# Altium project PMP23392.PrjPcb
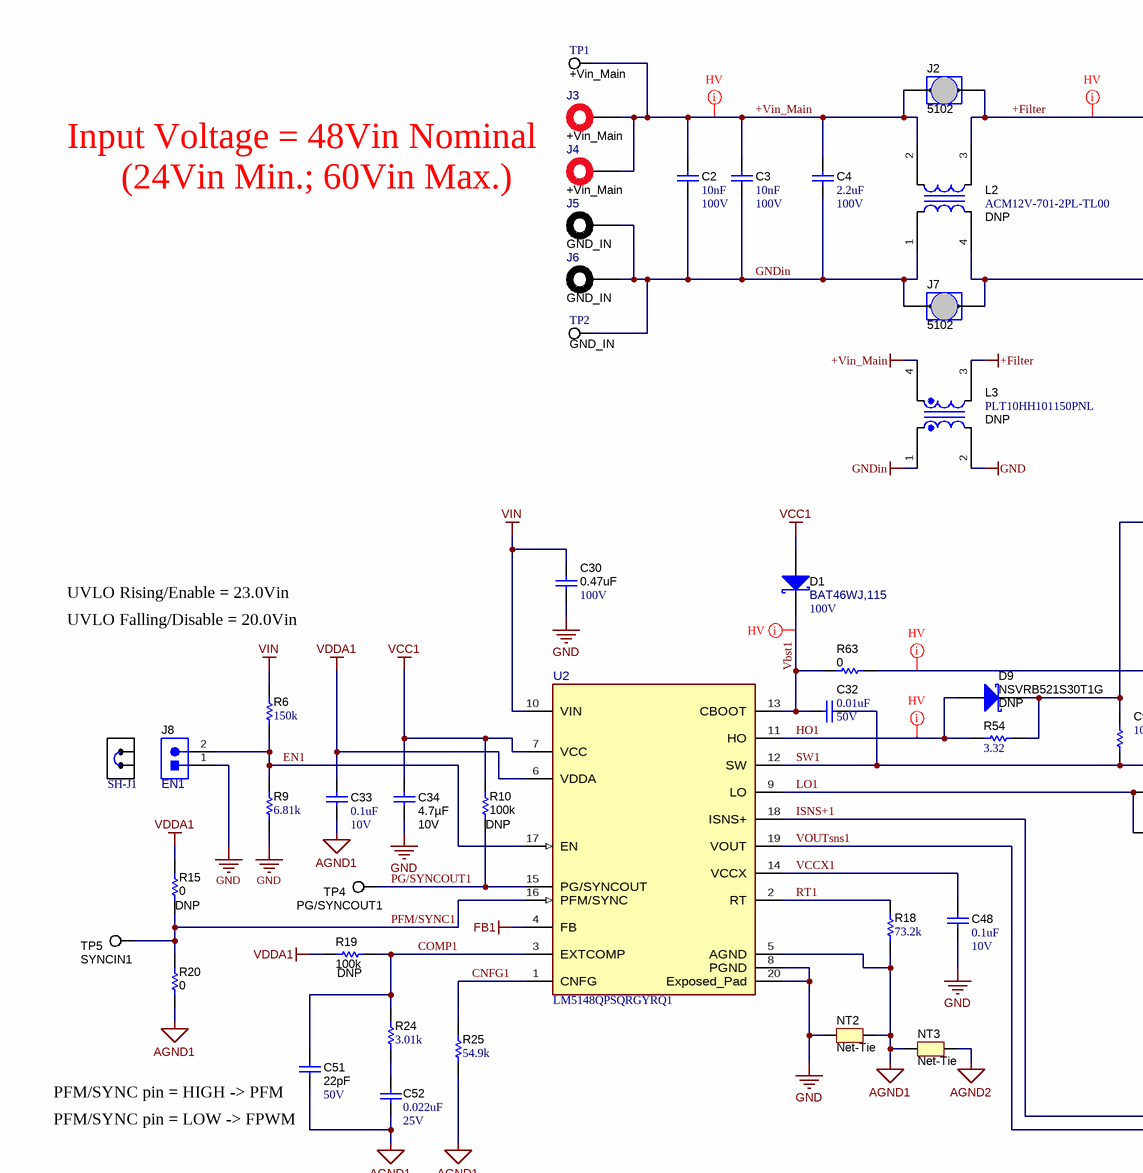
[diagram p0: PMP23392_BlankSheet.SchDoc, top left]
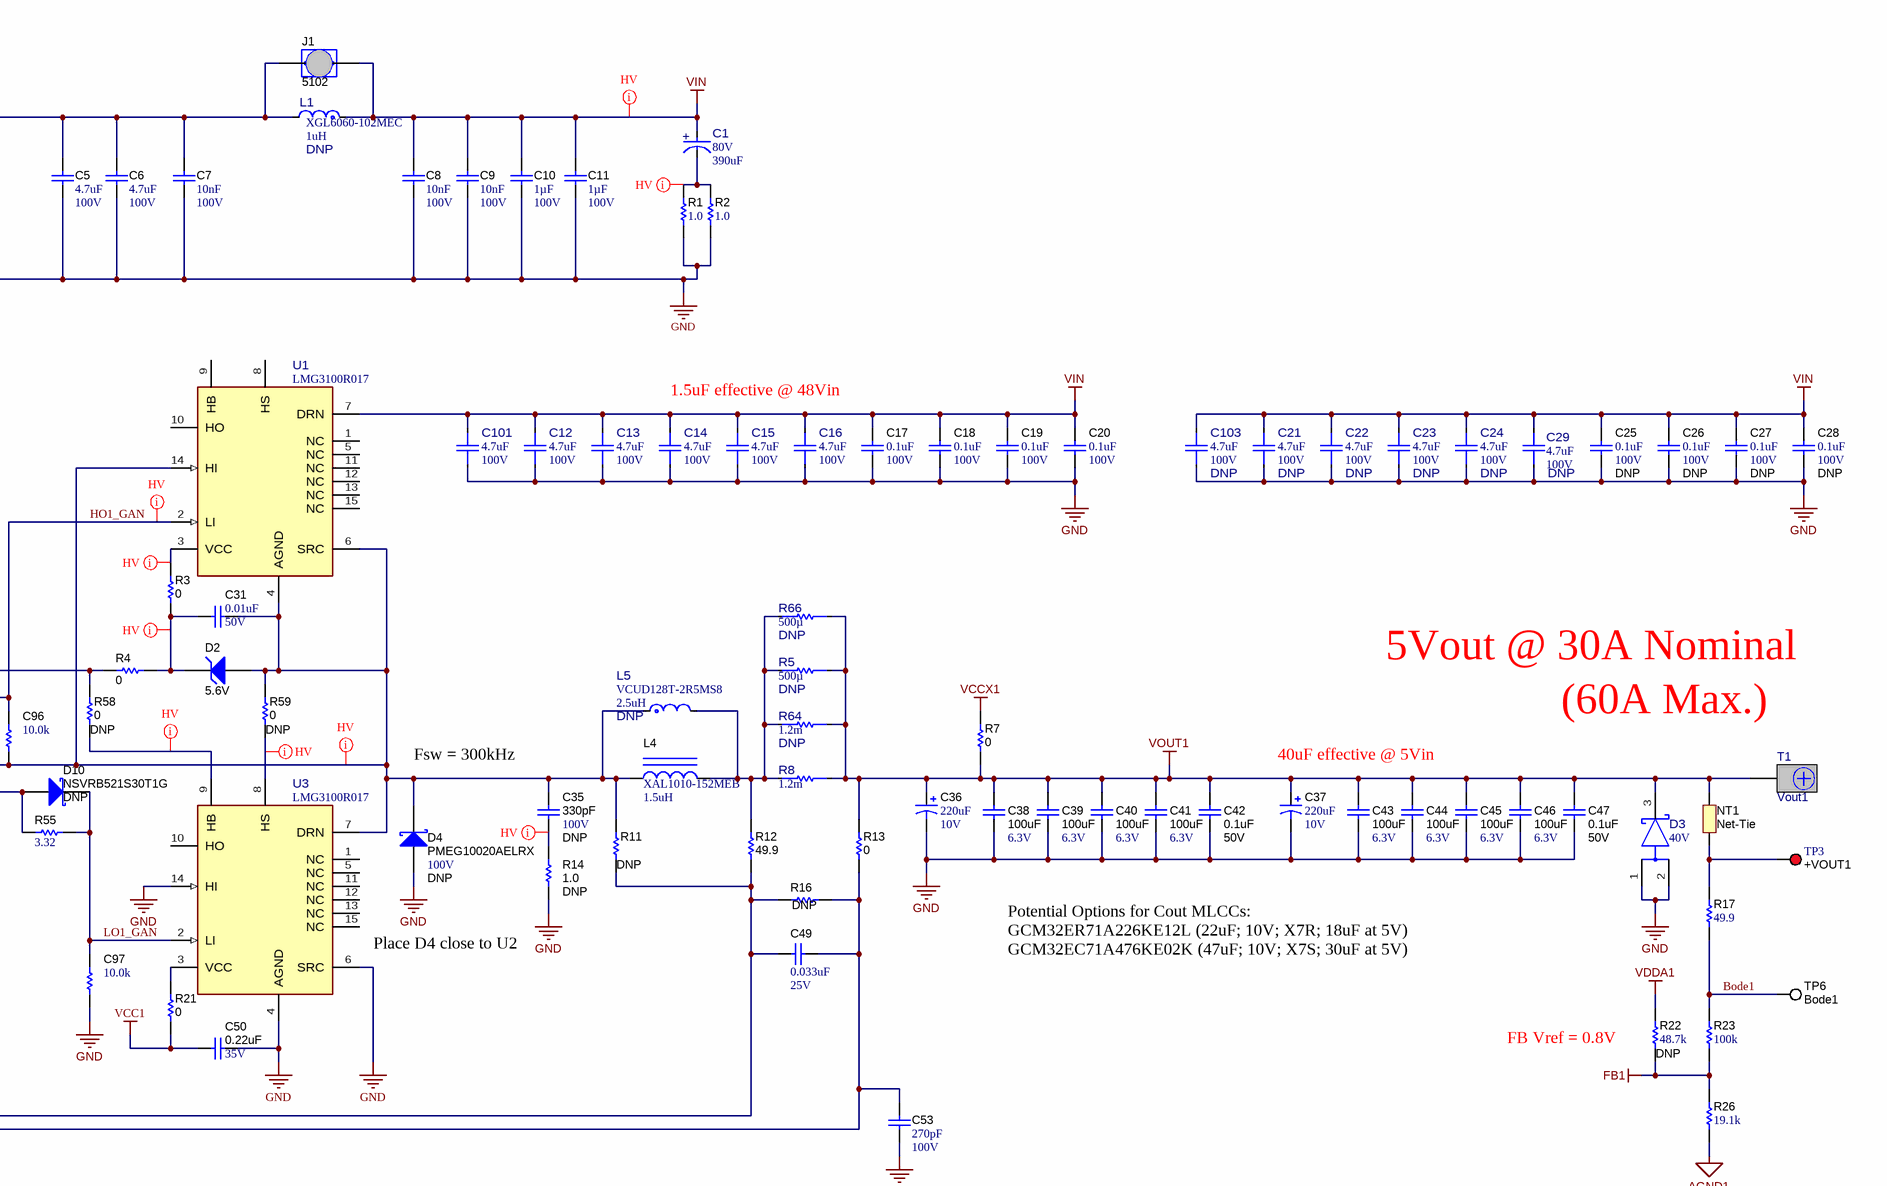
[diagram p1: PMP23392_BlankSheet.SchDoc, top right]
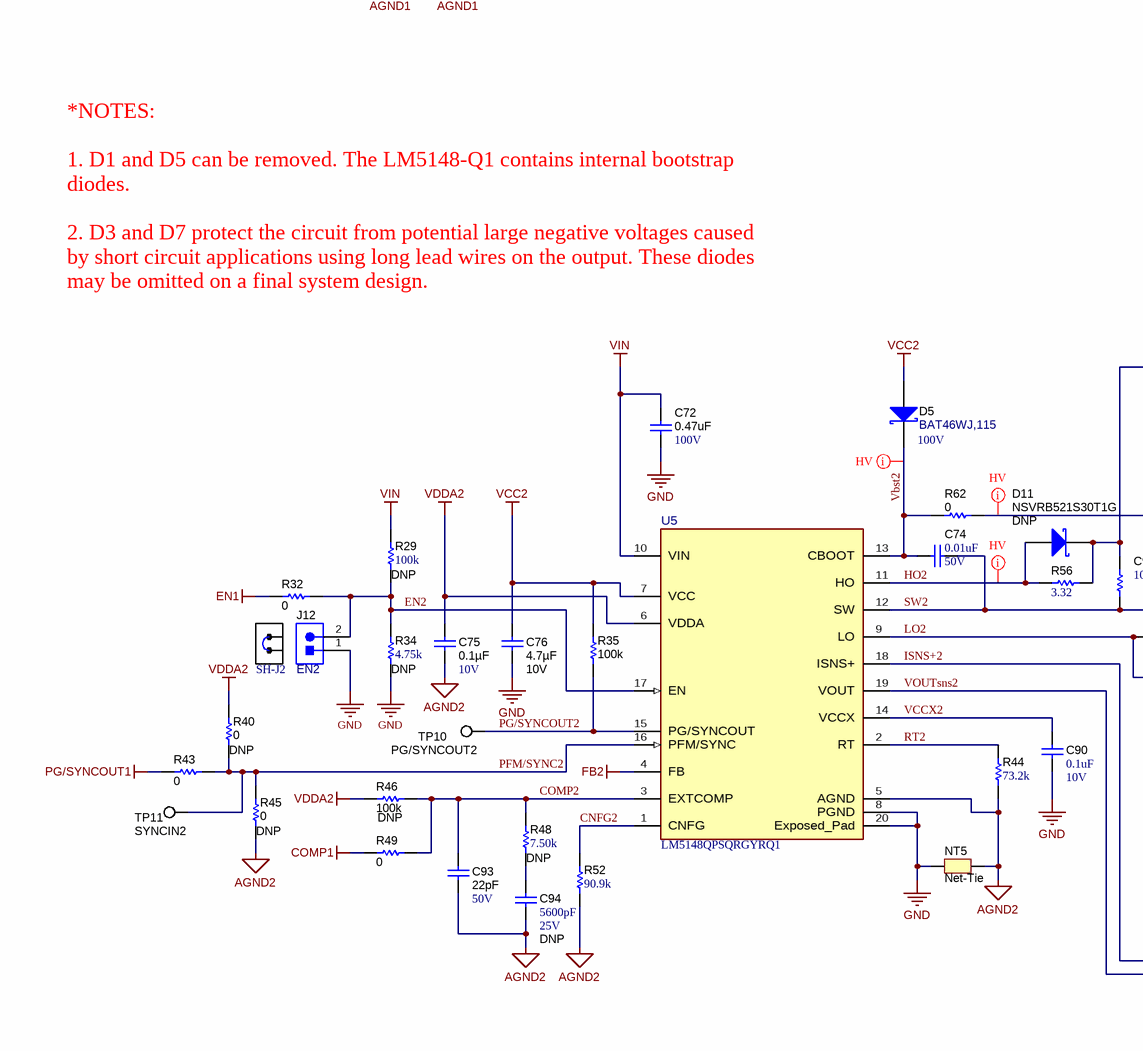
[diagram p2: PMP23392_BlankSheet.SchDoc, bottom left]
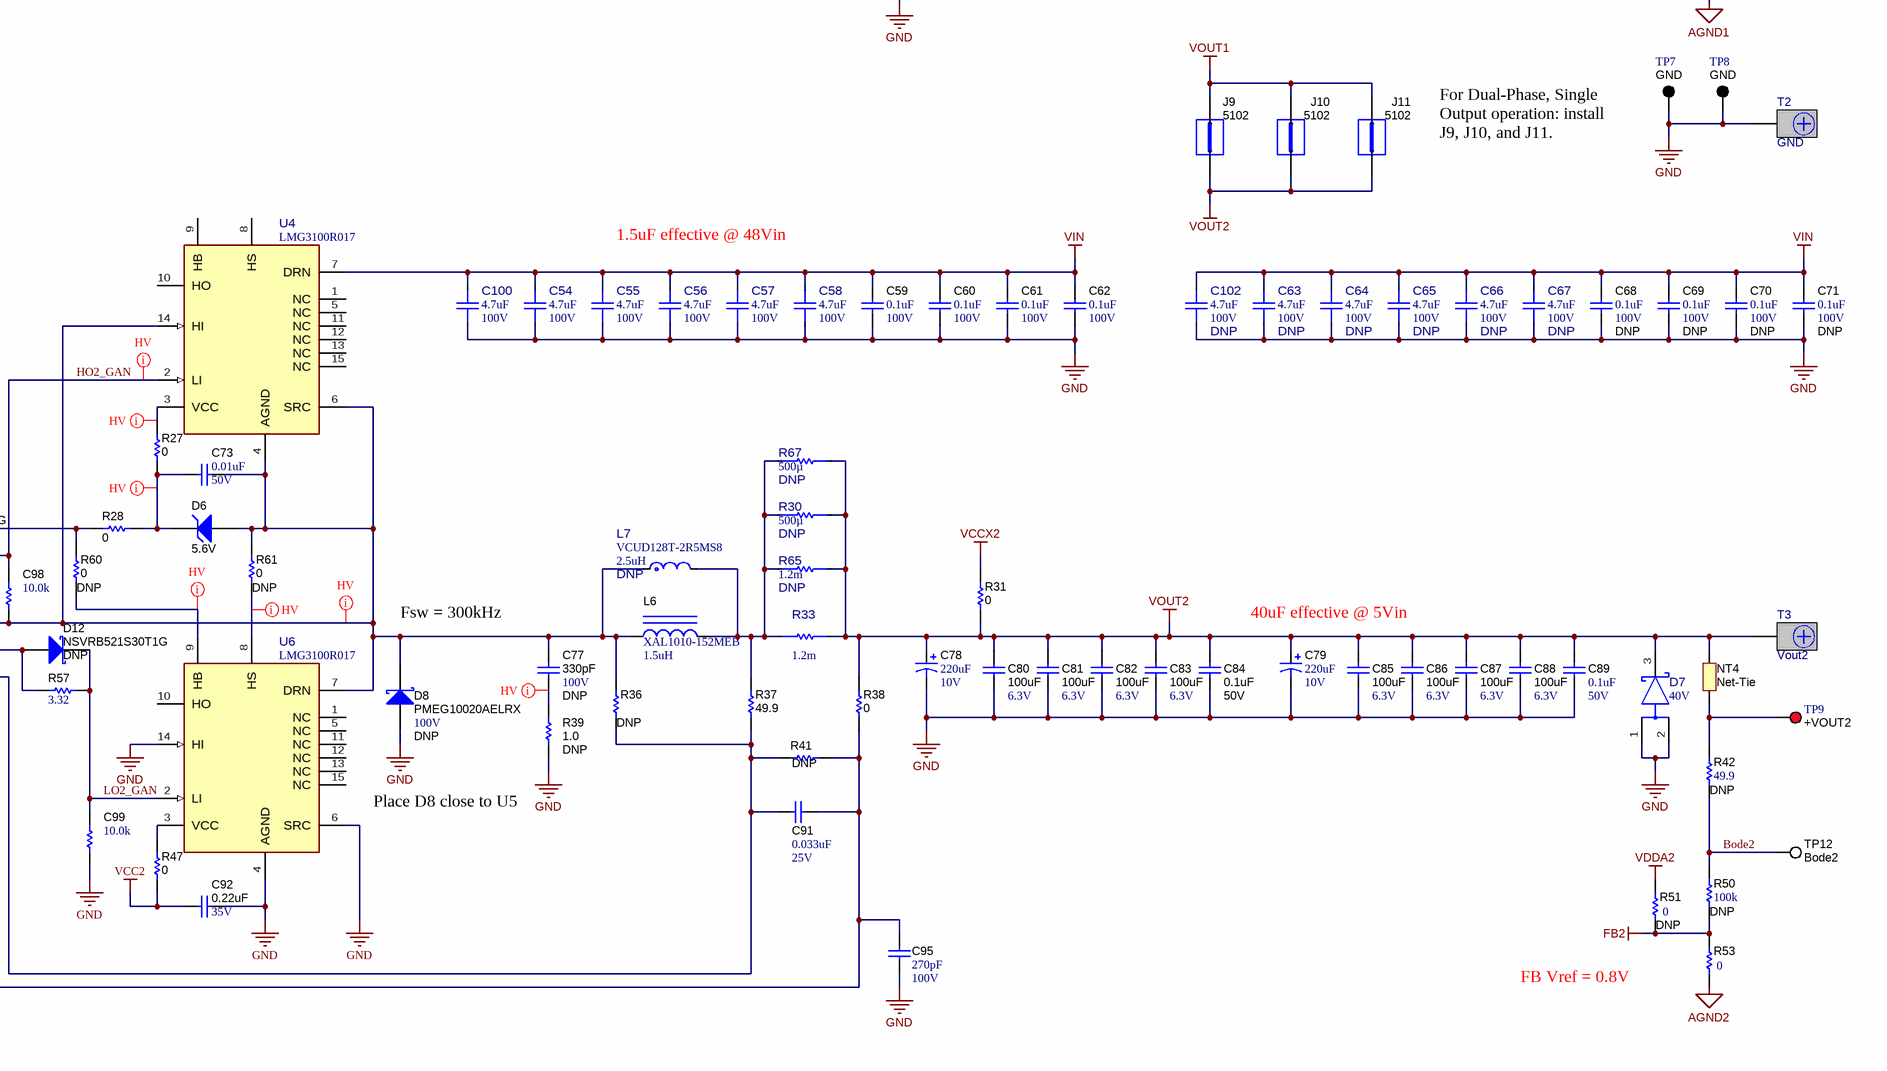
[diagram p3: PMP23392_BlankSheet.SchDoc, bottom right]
CopyrightYear: 2024; PCB_Layout: Hrag Kasparian; PCB_Rev: A; PRJ_Engineer: Hrag Kasparian; PRJ_Number: PMP23392; PRJ_Title: Dual-Phase LM5148-Q1 Buck Using GaN FETs; SCH_Rev: -1; TechSupport: http://www.ti.com/support; TID: PMP23392
2 sheets, 248 parts. Net scope: global (net labels, ports and power ports of the same name join across sheets).
Board file: PMP23392.PcbDoc
Sheets:
  PMP23392_BlankSheet.SchDoc
  PMP23392_Hardware.SchDoc

## Sheet PMP23392_BlankSheet.SchDoc
size 558 x 431 mm; Date: Not shown in title block; ApprovedBy: Not shown in title block; CheckedBy: Not shown in title block; Author: Not shown in title block; CompanyName: Not shown in title block; Engineer: Not shown in title block; Organization: Not shown in title block; Address1: Not shown in title block; Address2: Not shown in title block; Address3: Not shown in title block; Address4: Not shown in title block; DocumentNumber: 1; Revision: Use project parameter SCH_Rev; SheetNumber: 1; SheetTotal: 2; PageSetup: Record=PageOptions¦CenterHorizontal=True¦CenterVertical=True¦PrintScale=1.00¦XCorrection=1.00¦YCorrection=1.00¦PrintKind=0¦BorderSize=5000000¦LeftOffset=0¦BottomOffset=0¦Orientation=2¦PaperLength=1000¦PaperWidth=1000¦Scale=100¦PaperSource=15¦PrintQuality=600¦MediaType=1¦DitherType=10¦PaperKind=Letter¦PrintScaleMode=1; SPICEModelCacheOPLTMGFQ: <root> / <DocumentId>OPLTMGFQ</DocumentId> / <CacheFrame Number="0"> / <Model Name="zener" Kind="MDL"> / <Text>*ZENER / *Default Zener 10V @ 10mA / *Zener Diode Pinout: A,K / .MODEL ZENER D( BV=10 IBV=10E-3 )</Text> / </Model> / <Model Name="skydiode" Kind="MDL"> / <Text>*Default Schottky Diode / *Schottky Diode Pinout: A,K / .MODEL SKYDIODE D(EG=0.69 XTI=2)</Text> / </Model> / </CacheFrame> / </root>

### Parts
C1  VDC_V: 80V  ValueDisplayed: 390uF  [FP-EEE-TP1K391V_SMT_CAP_17MM0_17MM0-MFG]  (hidden comment: EEE-TP1K391V)
C2  Cap_F: 10nF  VDC_V: 100V  [0603_HV]  (hidden comment: GCM188R72A103KA37J)
C3  Cap_F: 10nF  VDC_V: 100V  [0603_HV]  (hidden comment: GCM188R72A103KA37J)
C4  VDC_V: 100V  ValueDisplayed: 2.2uF  [1206_180]  (hidden comment: CGA5L3X7S2A225K160AB)
C5  ValueDisplayed: 4.7uF  VDC_V: 100V  [1210_220]  (hidden comment: C3225X7S2A475K200AB)
C6  ValueDisplayed: 4.7uF  VDC_V: 100V  [1210_220]  (hidden comment: CGA6M3X7S2A475K200AB)
C7  Cap_F: 10nF  VDC_V: 100V  [0603L]  (hidden comment: GCM188R72A103KA37J)
C8  Cap_F: 10nF  VDC_V: 100V  [0603]  (hidden comment: GCM188R72A103KA37J)
C9  Cap_F: 10nF  VDC_V: 100V  [0603]  (hidden comment: GCM188R72A103KA37J)
C10  Cap_F: 1µF  VDC_V: 100V  [0805_150]  (hidden comment: 08051C105K4Z2A)
C11  Cap_F: 1µF  VDC_V: 100V  [0805_150]  (hidden comment: 08051C105K4Z2A)
C12  ValueDisplayed: 4.7uF  VDC_V: 100V  [FP-GCJ32DC72A475KE01L_1210-MFG]  (hidden comment: GCJ32DC72A475KE01L)
C13  ValueDisplayed: 4.7uF  VDC_V: 100V  [FP-GCJ32DC72A475KE01L_1210-MFG]  (hidden comment: GCJ32DC72A475KE01L)
C14  ValueDisplayed: 4.7uF  VDC_V: 100V  [FP-GCJ32DC72A475KE01L_1210-MFG]  (hidden comment: GCJ32DC72A475KE01L)
C15  ValueDisplayed: 4.7uF  VDC_V: 100V  [FP-GCJ32DC72A475KE01L_1210-MFG]  (hidden comment: GCJ32DC72A475KE01L)
C16  ValueDisplayed: 4.7uF  VDC_V: 100V  [FP-GCJ32DC72A475KE01L_1210-MFG]  (hidden comment: GCJ32DC72A475KE01L)
C17  VDC_V: 100V  ValueDisplayed: 0.1uF  [0603L]  (hidden comment: GCJ188R72A104KA01D)
C18  VDC_V: 100V  ValueDisplayed: 0.1uF  [0603L]  (hidden comment: GCJ188R72A104KA01D)
C19  VDC_V: 100V  ValueDisplayed: 0.1uF  [0603L]  (hidden comment: GCJ188R72A104KA01D)
C20  VDC_V: 100V  ValueDisplayed: 0.1uF  [0603L]  (hidden comment: GCJ188R72A104KA01D)
C21  DNP  ValueDisplayed: 4.7uF  VDC_V: 100V  [FP-GCJ32DC72A475KE01L_1210-MFG]
C22  DNP  ValueDisplayed: 4.7uF  VDC_V: 100V  [FP-GCJ32DC72A475KE01L_1210-MFG]
C23  DNP  ValueDisplayed: 4.7uF  VDC_V: 100V  [FP-GCJ32DC72A475KE01L_1210-MFG]
C24  DNP  ValueDisplayed: 4.7uF  VDC_V: 100V  [FP-GCJ32DC72A475KE01L_1210-MFG]
C25  DNP  VDC_V: 100V  ValueDisplayed: 0.1uF  [0603L]
C26  DNP  VDC_V: 100V  ValueDisplayed: 0.1uF  [0603L]
C27  DNP  VDC_V: 100V  ValueDisplayed: 0.1uF  [0603L]
C28  DNP  VDC_V: 100V  ValueDisplayed: 0.1uF  [0603L]
C29  DNP  ValueDisplayed: 4.7uF  VDC_V: 100V  [FP-GCJ32DC72A475KE01L_1210-MFG]
C30  value 0.47uF  Value1: 100V  [0805L]  (hidden comment: KAF21KR72A474KU)
C31  ValueDisplayed: 0.01uF  Value2: 50V  [0402]  (hidden comment: GRM155R71H103KA88D)
C32  ValueDisplayed: 0.01uF  Value2: 50V  [0402]  (hidden comment: GRM155R71H103KA88D)
C33  value 0.1uF  Value2: 10V  [0402L]  (hidden comment: C0402C104K8RACAUTO)
C34  Cap_F: 4.7µF  Value2: 10V  [0603L]  (hidden comment: GRM188Z71A475ME15D)
C35  DNP  value 330pF  Value1: 100V  [0603L]
C36  VDC_V: 10V  ValueDisplayed: 220uF  [7343-31]
C37  VDC_V: 10V  ValueDisplayed: 220uF  [7343-31]
C38  value 100uF  Value1: 6.3V  [1210L]  (hidden comment: GRT32EC70J107ME13K)
C39  value 100uF  Value1: 6.3V  [1210L]  (hidden comment: GRT32EC70J107ME13K)
C40  value 100uF  Value1: 6.3V  [1210L]  (hidden comment: GRT32EC70J107ME13K)
C41  value 100uF  Value1: 6.3V  [1210L]  (hidden comment: GRT32EC70J107ME13K)
C42  Value2: 50V  Cap_F: 0.1uF  [0603L]  (hidden comment: C0603C104K5RACTU)
C43  value 100uF  Value1: 6.3V  [1210L]  (hidden comment: GRT32EC70J107ME13K)
C44  value 100uF  Value1: 6.3V  [1210L]  (hidden comment: GRT32EC70J107ME13K)
C45  value 100uF  Value1: 6.3V  [1210L]  (hidden comment: GRT32EC70J107ME13K)
C46  value 100uF  Value1: 6.3V  [1210L]  (hidden comment: GRT32EC70J107ME13K)
C47  ValueDisplayed: 0.1uF  Value2: 50V  [0603L]  (hidden comment: Capacitor)
C48  value 0.1uF  Value2: 10V  [0402L]  (hidden comment: C0402C104K8RACAUTO)
C49  ValueDisplayed: 0.033uF  Value2: 25V  [0402L]  (hidden comment: CGA2B1X7R1E333K050BC)
C50  value 0.22uF  Value1: 35V  [0402L]  (hidden comment: CGA2B1X7R1V224K050BC)
C51  ValueDisplayed: 22pF  Value2: 50V  [0402L]  (hidden comment: CGA2B2NP01H220J050BA)
C52  ValueDisplayed: 0.022uF  VDC_V: 25V  [0402L]  (hidden comment: GCM155R71E223KA55D)
C53  ValueDisplayed: 270pF  VDC_V: 100V  [0402L]  (hidden comment: GRM155R72A271KA01D)
C54  ValueDisplayed: 4.7uF  VDC_V: 100V  [FP-GCJ32DC72A475KE01L_1210-MFG]  (hidden comment: GCJ32DC72A475KE01L)
C55  ValueDisplayed: 4.7uF  VDC_V: 100V  [FP-GCJ32DC72A475KE01L_1210-MFG]  (hidden comment: GCJ32DC72A475KE01L)
C56  ValueDisplayed: 4.7uF  VDC_V: 100V  [FP-GCJ32DC72A475KE01L_1210-MFG]  (hidden comment: GCJ32DC72A475KE01L)
C57  ValueDisplayed: 4.7uF  VDC_V: 100V  [FP-GCJ32DC72A475KE01L_1210-MFG]  (hidden comment: GCJ32DC72A475KE01L)
C58  ValueDisplayed: 4.7uF  VDC_V: 100V  [FP-GCJ32DC72A475KE01L_1210-MFG]  (hidden comment: GCJ32DC72A475KE01L)
C59  VDC_V: 100V  ValueDisplayed: 0.1uF  [0603L]  (hidden comment: GCJ188R72A104KA01D)
C60  VDC_V: 100V  ValueDisplayed: 0.1uF  [0603L]  (hidden comment: GCJ188R72A104KA01D)
C61  VDC_V: 100V  ValueDisplayed: 0.1uF  [0603L]  (hidden comment: GCJ188R72A104KA01D)
C62  VDC_V: 100V  ValueDisplayed: 0.1uF  [0603L]  (hidden comment: GCJ188R72A104KA01D)
C63  DNP  ValueDisplayed: 4.7uF  VDC_V: 100V  [FP-GCJ32DC72A475KE01L_1210-MFG]
C64  DNP  ValueDisplayed: 4.7uF  VDC_V: 100V  [FP-GCJ32DC72A475KE01L_1210-MFG]
C65  DNP  ValueDisplayed: 4.7uF  VDC_V: 100V  [FP-GCJ32DC72A475KE01L_1210-MFG]
C66  DNP  ValueDisplayed: 4.7uF  VDC_V: 100V  [FP-GCJ32DC72A475KE01L_1210-MFG]
C67  DNP  ValueDisplayed: 4.7uF  VDC_V: 100V  [FP-GCJ32DC72A475KE01L_1210-MFG]
C68  DNP  VDC_V: 100V  ValueDisplayed: 0.1uF  [0603L]
C69  DNP  VDC_V: 100V  ValueDisplayed: 0.1uF  [0603L]
C70  DNP  VDC_V: 100V  ValueDisplayed: 0.1uF  [0603L]
C71  DNP  VDC_V: 100V  ValueDisplayed: 0.1uF  [0603L]
C72  value 0.47uF  Value1: 100V  [0805L]  (hidden comment: KAF21KR72A474KU)
C73  ValueDisplayed: 0.01uF  Value2: 50V  [0402]  (hidden comment: GRM155R71H103KA88D)
C74  ValueDisplayed: 0.01uF  Value2: 50V  [0402]  (hidden comment: GRM155R71H103KA88D)
C75  ValueDisplayed: 0.1µF  Value2: 10V  [0402L]  (hidden comment: C0402C104K8RACAUTO)
C76  Cap_F: 4.7µF  Value2: 10V  [0603L]  (hidden comment: GRM188Z71A475ME15D)
C77  DNP  value 330pF  Value1: 100V  [0603L]
C78  VDC_V: 10V  ValueDisplayed: 220uF  [7343-31]
C79  VDC_V: 10V  ValueDisplayed: 220uF  [7343-31]
C80  value 100uF  Value1: 6.3V  [1210L]  (hidden comment: GRT32EC70J107ME13K)
C81  value 100uF  Value1: 6.3V  [1210L]  (hidden comment: GRT32EC70J107ME13K)
C82  value 100uF  Value1: 6.3V  [1210L]  (hidden comment: GRT32EC70J107ME13K)
C83  value 100uF  Value1: 6.3V  [1210L]  (hidden comment: GRT32EC70J107ME13K)
C84  value 0.1uF  Value2: 50V  [0603L]  (hidden comment: C0603C104K5RACTU)
C85  value 100uF  Value1: 6.3V  [1210L]  (hidden comment: GRT32EC70J107ME13K)
C86  value 100uF  Value1: 6.3V  [1210L]  (hidden comment: GRT32EC70J107ME13K)
C87  value 100uF  Value1: 6.3V  [1210L]  (hidden comment: GRT32EC70J107ME13K)
C88  value 100uF  Value1: 6.3V  [1210L]  (hidden comment: GRT32EC70J107ME13K)
C89  value 0.1uF  VDC_V: 50V  [0603L]  (hidden comment: C0603C104K5RACTU)
C90  value 0.1uF  Value2: 10V  [0402L]  (hidden comment: C0402C104K8RACAUTO)
C91  ValueDisplayed: 0.033uF  Value2: 25V  [0402L]  (hidden comment: CGA2B1X7R1E333K050BC)
C92  value 0.22uF  Value1: 35V  [0402L]  (hidden comment: CGA2B1X7R1V224K050BC)
C93  ValueDisplayed: 22pF  Value2: 50V  [0402L]  (hidden comment: CGA2B2NP01H220J050BA)
C94  DNP  ValueDisplayed: 5600pF  VDC_V: 25V  [0402L]
C95  ValueDisplayed: 270pF  VDC_V: 100V  [0402L]  (hidden comment: GRM155R72A271KA01D)
C96  value 10.0k  [0402]  (hidden comment: CRCW040210K0FKED)
C97  value 10.0k  [0402]  (hidden comment: CRCW040210K0FKED)
C98  value 10.0k  [0402]  (hidden comment: CRCW040210K0FKED)
C99  value 10.0k  [0402]  (hidden comment: CRCW040210K0FKED)
C100  ValueDisplayed: 4.7uF  VDC_V: 100V  [FP-GCJ32DC72A475KE01L_1210-MFG]  (hidden comment: GCJ32DC72A475KE01L)
C101  ValueDisplayed: 4.7uF  VDC_V: 100V  [FP-GCJ32DC72A475KE01L_1210-MFG]  (hidden comment: GCJ32DC72A475KE01L)
C102  DNP  ValueDisplayed: 4.7uF  VDC_V: 100V  [FP-GCJ32DC72A475KE01L_1210-MFG]
C103  DNP  ValueDisplayed: 4.7uF  VDC_V: 100V  [FP-GCJ32DC72A475KE01L_1210-MFG]
D1  BAT46WJ,115  value 100V  [SOD-323F]
D2  value 5.6V  [SOD-323]  (hidden comment: TDZ5V6J,115)
D3  value 40V  [FP-SS10P4HM3_A/H_SMPC-MFG]  (hidden comment: SS10P4HM3_A/H)
D4  DNP  value 100V  PartNumber: PMEG10020AELRX  [SOD-123]
D5  BAT46WJ,115  value 100V  [SOD-323F]
D6  value 5.6V  [SOD-323]  (hidden comment: TDZ5V6J,115)
D7  value 40V  [FP-SS10P4HM3_A/H_SMPC-MFG]  (hidden comment: SS10P4HM3_A/H)
D8  DNP  value 100V  PartNumber: PMEG10020AELRX  [SOD-123]
D9  DNP  PartNumber: NSVRB521S30T1G  [SOD-523]
D10  DNP  PartNumber: NSVRB521S30T1G  [SOD-523]
D11  DNP  PartNumber: NSVRB521S30T1G  [SOD-523]
D12  DNP  PartNumber: NSVRB521S30T1G  [SOD-523]
J1  PartNumber: 5102  [Keystone_5102]
J2  PartNumber: 5102  [Keystone_5102]
J3  +Vin_Main  [Cinch_108-0902-001]
J4  +Vin_Main  [Cinch_108-0902-001]
J5  GND_IN  [Cinch_108-0903-001]
J6  GND_IN  [Cinch_108-0903-001]
J7  PartNumber: 5102  [Keystone_5102]
J8  EN1  [TSW-102-07-G-S]
J9  PartNumber: 5102  [Keystone_5102]
J10  PartNumber: 5102  [Keystone_5102]
J11  PartNumber: 5102  [Keystone_5102]
J12  EN2  [TSW-102-07-G-S]
L1  DNP  value 1uH  Part Number: XGL6060-102MEC  [FP-XGL6060-102MEC_SMT2_6MM51_6MM71-MFG]
L2  DNP  PartNumber: ACM12V-701-2PL-TL00  [TDK_ACM12V]
L3  DNP  PartNumber: PLT10HH101150PNL  [MuRata_PLT10H]
L4  value 1.5uH  [XAL1010]  (hidden comment: XAL1010-152MEB)
L5  DNP  value 2.5uH  Part Number: VCUD128T-2R5MS8  [FP-VCUD128T-2R5MS8_SMT_IND_13MM3_12MM8-MFG]
L6  value 1.5uH  [XAL1010]  (hidden comment: XAL1010-152MEB)
L7  DNP  value 2.5uH  PartNumber: VCUD128T-2R5MS8  [FP-VCUD128T-2R5MS8_SMT_IND_13MM3_12MM8-MFG]
NT1  Net-Tie  [Net-Tie_10mil]  (net tie, no BOM)
NT2  Net-Tie  [Net-Tie_10mil]  (net tie, no BOM)
NT3  Net-Tie  [Net-Tie_10mil]  (net tie, no BOM)
NT4  Net-Tie  [Net-Tie_10mil]  (net tie, no BOM)
NT5  Net-Tie  [Net-Tie_10mil]  (net tie, no BOM)
R1  ValueDisplayed: 1.0  [2512]  (hidden comment: CRCW25121R00JNEG)
R2  ValueDisplayed: 1.0  [2512]  (hidden comment: CRCW25121R00JNEG)
R3  ValueDisplayed: 0  [0402L]  (hidden comment: CRCW04020000Z0EDHP)
R4  ValueDisplayed: 0  [0402L]  (hidden comment: CRCW04020000Z0EDHP)
R5  DNP  value 500µ  [FP-PML100HZPJV0L5_1225-MFG]
R6  ValueDisplayed: 150k  [0603L]  (hidden comment: CRCW0603150KFKEA)
R7  ValueDisplayed: 0  [0402L]  (hidden comment: CRCW04020000Z0EDHP)
R8  Res_ohm: 1.2m  [FP-Y14830R00120F9R_2512-MFG]  (hidden comment: Y14830R00120F9R)
R9  ValueDisplayed: 6.81k  [0402L]  (hidden comment: CRCW04026K81FKED)
R10  DNP  ValueDisplayed: 100k  [0402L]
R11  DNP  [0603L]
R12  ValueDisplayed: 49.9  [0402L]  (hidden comment: CRCW040249R9FKED)
R13  Value1: 0  [FP-RMCF0402ZT0R00_0402 (1005 metric)-0]  (hidden comment: RMCF0402ZT0R00)
R14  DNP  value 1.0  [1210L]
R15  DNP  ValueDisplayed: 0  [0402L]
R16  DNP  [0402L]
R17  ValueDisplayed: 49.9  [0603L]  (hidden comment: CRCW060349R9FKEA)
R18  ValueDisplayed: 73.2k  [0402L]  (hidden comment: CRCW040273K2FKED)
R19  DNP  ValueDisplayed: 100k  [0402L]
R20  ValueDisplayed: 0  [0402L]
R21  ValueDisplayed: 0  [0402L]  (hidden comment: CRCW04020000Z0EDHP)
R22  DNP  ValueDisplayed: 48.7k  [0402L]
R23  ValueDisplayed: 100k  [0402L]  (hidden comment: RMCF0402FT100K)
R24  ValueDisplayed: 3.01k  [0402L]  (hidden comment: CRCW04023K01FKED)
R25  ValueDisplayed: 54.9k  [0402L]  (hidden comment: CRCW040254K9FKED)
R26  ValueDisplayed: 19.1k  [0402L]  (hidden comment: CRCW040219K1FKED)
R27  ValueDisplayed: 0  [0402L]  (hidden comment: CRCW04020000Z0EDHP)
R28  ValueDisplayed: 0  [0402L]  (hidden comment: CRCW04020000Z0EDHP)
R29  DNP  ValueDisplayed: 100k  [0603L]
R30  DNP  value 500µ  [FP-PML100HZPJV0L5_1225-MFG]
R31  ValueDisplayed: 0  [0402L]  (hidden comment: CRCW04020000Z0EDHP)
R32  ValueDisplayed: 0  [0402L]  (hidden comment: CRCW04020000Z0EDHP)
R33  Res_ohm: 1.2m  [FP-Y14830R00120F9R_2512-MFG]  (hidden comment: Y14830R00120F9R)
R34  DNP  ValueDisplayed: 4.75k  [0402L]
R35  ValueDisplayed: 100k  [0402L]  (hidden comment: RMCF0402FT100K)
R36  DNP  [0603L]
R37  ValueDisplayed: 49.9  [0402L]  (hidden comment: CRCW040249R9FKED)
R38  Value1: 0  [FP-RMCF0402ZT0R00_0402 (1005 metric)-0]  (hidden comment: RMCF0402ZT0R00)
R39  DNP  value 1.0  [1210L]
R40  DNP  ValueDisplayed: 0  [0402L]
R41  DNP  [0402L]
R42  DNP  ValueDisplayed: 49.9  [0603L]
R43  ValueDisplayed: 0  [0402L]  (hidden comment: CRCW04020000Z0EDHP)
R44  ValueDisplayed: 73.2k  [0402L]  (hidden comment: CRCW040273K2FKED)
R45  DNP  ValueDisplayed: 0  [0402L]
R46  DNP  ValueDisplayed: 100k  [0402L]
R47  ValueDisplayed: 0  [0402L]  (hidden comment: CRCW04020000Z0EDHP)
R48  DNP  ValueDisplayed: 7.50k  [0402L]
R49  ValueDisplayed: 0  [0402L]  (hidden comment: CRCW04020000Z0EDHP)
R50  DNP  ValueDisplayed: 100k  [0402L]
R51  DNP  value 0  [FP-RMCF0402ZT0R00_0402 (1005 metric)-0]
R52  ValueDisplayed: 90.9k  [0402L]  (hidden comment: CRCW040290K9FKED)
R53  value 0  [FP-RMCF0402ZT0R00_0402 (1005 metric)-0]
R54  ValueDisplayed: 3.32  [0402L]  (hidden comment: CRCW04023R32FKED)
R55  ValueDisplayed: 3.32  [0402L]  (hidden comment: CRCW04023R32FKED)
R56  ValueDisplayed: 3.32  [0402L]  (hidden comment: CRCW04023R32FKED)
R57  ValueDisplayed: 3.32  [0402L]  (hidden comment: CRCW04023R32FKED)
R58  DNP  ValueDisplayed: 0  [0402L]
R59  DNP  ValueDisplayed: 0  [0402L]
R60  DNP  ValueDisplayed: 0  [0402L]
R61  DNP  ValueDisplayed: 0  [0402L]
R62  ValueDisplayed: 0  [0402L]
R63  ValueDisplayed: 0  [0402L]
R64  DNP  Res_ohm: 1.2m  [FP-Y14830R00120F9R_2512-MFG]
R65  DNP  Res_ohm: 1.2m  [FP-Y14830R00120F9R_2512-MFG]
R66  DNP  value 500µ  [FP-PML100HZPJV0L5_1225-MFG]
R67  DNP  value 500µ  [FP-PML100HZPJV0L5_1225-MFG]
SH-J1  60900213421  [Wurth_60900213421]  (value not drawn)
SH-J2  60900213421  [Wurth_60900213421]  (value not drawn)
T1  Vout1  [CB70-14-CY]
T2  GND  [CB70-14-CY]
T3  Vout2  [CB70-14-CY]
TP1  +Vin_Main  [Testpoint_Keystone_Compact]
TP2  GND_IN  [Testpoint_Keystone_Compact]
TP3  +VOUT1  [Keystone5010]
TP4  PG/SYNCOUT1  [Keystone5012]
TP5  SYNCIN1  [Keystone5012]
TP6  Bode1  [Keystone5012]
TP7  GND  [Keystone5011]
TP8  GND  [Keystone5011]
TP9  +VOUT2  [Keystone5010]
TP10  PG/SYNCOUT2  [Keystone5012]
TP11  SYNCIN2  [Keystone5012]
TP12  Bode2  [Keystone5012]
U1  LMG3100R017  [VBE0015A-MFG]
U2  LM5148QPSQRGYRQ1  [RGY0019B-MFG]
U3  LMG3100R017  [VBE0015A-MFG]
U4  LMG3100R017  [VBE0015A-MFG]
U5  LM5148QPSQRGYRQ1  [RGY0019B-MFG]
U6  LMG3100R017  [VBE0015A-MFG]

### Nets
+Filter: C5.2 C6.2 C7.1 J1.2 J2.1 L1.2 L2.3 L3.3
+Vin_Main: C2.1 C3.1 C4.1 J2.2 J3.1 J4.1 L2.2 L3.4 TP1.1
AGND1: C33.1 C51.2 C52.2 NT2.2 NT3.1 R18.2 R20.2 R25.1 R26.1 U2.5(AGND)
AGND2: C75.1 C93.2 C94.2 NT3.2 NT5.2 R44.2 R45.2 R52.1 R53.2 U5.5(AGND)
COMP1: C51.1 R19.1 R24.2 R49.2 U2.3(EXTCOMP)
EN1: J8.2 R6.1 R9.2 R32.2 U2.17(EN)
FB1: R22.2 R23.1 R26.2 U2.4(FB)
FB2: R50.1 R51.2 R53.1 U5.4(FB)
GND: C5.1 C6.1 C7.2 C8.2 C9.2 C10.2 C11.2 C12.1 C13.1 C14.1 C15.1 C16.1 C17.2 C18.2 C19.2 C20.2 C21.1 C22.1 C23.1 C24.1 C25.2 C26.2 C27.2 C28.2 C29.1 C30.2 C34.2 C36.2(-) C37.2(-) C38.2 C39.2 C40.2 C41.2 C42.2 C43.2 C44.2 C45.2 C46.2 C47.2 C48.1 C50.2 C53.1 C54.1 C55.1 C56.1 C57.1 C58.1 C59.2 C60.2 C61.2 C62.2 C63.1 C64.1 C65.1 C66.1 C67.1 C68.2 C69.2 C70.2 C71.2 C72.2 C76.2 C78.2(-) C79.2(-) C80.2 C81.2 C82.2 C83.2 C84.2 C85.2 C86.2 C87.2 C88.2 C89.2 C90.1 C92.2 C95.1 C97.1 C99.1 C100.1 C101.1 C102.1 C103.1 D3.1(Anode) D3.2(Anode) D4.2(A) D7.1(Anode) D7.2(Anode) D8.2(A) J7.1 J8.1 J12.1 L2.4 L3.2 NT2.1 NT5.1 R1.1 R2.1 R9.1 R14.1 R34.1 R39.1 T2.1 TP7.1 TP8.1 U2.8(PGND) U2.20(Exposed_Pad) U3.4(AGND) U3.6(SRC) U3.14(HI) U5.8(PGND) U5.20(Exposed_Pad) U6.4(AGND) U6.6(SRC) U6.14(HI)
GNDin: C2.2 C3.2 C4.2 J5.1 J6.1 J7.2 L2.1 L3.1 TP2.1
PG/SYNCOUT1: R10.1 R43.2 TP4.1 U2.15(PG/SYNCOUT)
VCC1: C34.1 C50.1 D1.2(A) R10.2 R21.1 U2.7(VCC)
VCC2: C76.1 C92.1 D5.2(A) R35.2 R47.1 U5.7(VCC)
VCCX1: C48.2 R7.2 U2.14(VCCX)
VCCX2: C90.2 R31.1 U5.14(VCCX)
VDDA1: C33.2 R15.1 R19.2 R22.1 U2.6(VDDA)
VDDA2: C75.2 R40.1 R46.1 R51.1 U5.6(VDDA)
VIN: C1.2(ANODE) C8.1 C9.1 C10.1 C11.1 C12.2 C13.2 C14.2 C15.2 C16.2 C17.1 C18.1 C19.1 C20.1 C21.2 C22.2 C23.2 C24.2 C25.1 C26.1 C27.1 C28.1 C29.2 C30.1 C54.2 C55.2 C56.2 C57.2 C58.2 C59.1 C60.1 C61.1 C62.1 C63.2 C64.2 C65.2 C66.2 C67.2 C68.1 C69.1 C70.1 C71.1 C72.1 C100.2 C101.2 C102.2 C103.2 J1.1 L1.1 R6.2 R29.2 U1.7(DRN) U2.10(VIN) U4.7(DRN) U5.10(VIN)
VOUT1: C36.1(+) C37.1(+) C38.1 C39.1 C40.1 C41.1 C42.1 C43.1 C44.1 C45.1 C46.1 C47.1 D3.3(Cathode) J9.2 J10.2 J11.2 NT1.2 R5.2 R7.1 R8.2 R13.2 R64.2 R66.2 T1.1
VOUT2: C78.1(+) C79.1(+) C80.1 C81.1 C82.1 C83.1 C84.1 C85.1 C86.1 C87.1 C88.1 C89.1 D7.3(Cathode) J9.1 J10.1 J11.1 NT4.2 R30.2 R31.2 R33.2 R38.2 R65.2 R67.2 T3.1
Bode1: R17.1 R23.2 TP6.1
Bode2: R42.1 R50.2 TP12.1
CNFG1: R25.2 U2.1(CNFG)
CNFG2: R52.2 U5.1(CNFG)
COMP2: C93.1 R46.2 R48.2 R49.1 U5.3(EXTCOMP)
EN2: J12.2 R29.1 R32.1 R34.2 U5.17(EN)
HO1: D9.2(A) R54.1 U2.11(HO)
HO1_GAN: C96.2 D9.1(K) R54.2 U1.2(LI)
HO2: D11.2(A) R56.1 U5.11(HO)
HO2_GAN: C98.2 D11.1(K) R56.2 U4.2(LI)
ISNS+1: C49.2 R11.1 R12.1 R16.2 U2.18(ISNS+)
ISNS+2: C91.2 R36.1 R37.1 R41.2 U5.18(ISNS+)
LO1: D10.2(A) R55.1 U2.9(LO)
LO1_GAN: C97.2 D10.1(K) R55.2 U3.2(LI)
LO2: D12.2(A) R57.1 U5.9(LO)
LO2_GAN: C99.2 D12.1(K) R57.2 U6.2(LI)
PFM/SYNC1: R15.2 R20.1 TP5.1 U2.16(PFM/SYNC)
PFM/SYNC2: R40.2 R43.1 R45.1 TP11.1 U5.16(PFM/SYNC)
PG/SYNCOUT2: R35.1 TP10.1 U5.15(PG/SYNCOUT)
RT1: R18.1 U2.2(RT)
RT2: R44.1 U5.2(RT)
SW1: C31.2 C32.2 C35.1 C96.1 D2.2(A) D4.1(K) L4.1 L5.1 R11.2 R59.2 U1.4(AGND) U1.6(SRC) U1.14(HI) U2.12(SW) U3.7(DRN)
SW2: C73.2 C74.2 C77.1 C98.1 D6.2(A) D8.1(K) L6.1 L7.1 R36.2 R61.2 U4.4(AGND) U4.6(SRC) U4.14(HI) U5.12(SW) U6.7(DRN)
Vbst1: C32.1 D1.1(K) R63.2 U2.13(CBOOT)
Vbst2: C74.1 D5.1(K) R62.2 U5.13(CBOOT)
VOUTsns1: C49.1 C53.2 R13.1 R16.1 U2.19(VOUT)
VOUTsns2: C91.1 C95.2 R38.1 R41.1 U5.19(VOUT)
NetC1_1: C1.1(CATHODE) R1.2 R2.2
NetC31_1: C31.1 D2.1(K) R3.1 R4.1
NetC35_2: C35.2 R14.2
NetC52_1: C52.1 R24.1
NetC73_1: C73.1 D6.1(K) R27.1 R28.1
NetC77_2: C77.2 R39.2
NetC94_1: C94.1 R48.1
NetL4_2: L4.2 L5.2 R5.1 R8.1 R12.2 R64.1 R66.1
NetL6_2: L6.2 L7.2 R30.1 R33.1 R37.2 R65.1 R67.1
NetNT1_1: NT1.1 R17.2 TP3.1
NetNT4_1: NT4.1 R42.2 TP9.1
NetR3_2: R3.2 U1.3(VCC)
NetR4_2: R4.2 R58.2 R63.1
NetR21_2: R21.2 U3.3(VCC)
NetR27_2: R27.2 U4.3(VCC)
NetR28_2: R28.2 R60.2 R62.1
NetR47_2: R47.2 U6.3(VCC)
NetR58_1: R58.1 U3.9(HB)
NetR59_1: R59.1 U3.8(HS)
NetR60_1: R60.1 U6.9(HB)
NetR61_1: R61.1 U6.8(HS)

Not connected (* = marked no-connect by the designer): U1 1(NC) 5(NC) 8(HS) 9(HB) 10(HO) 11(NC) 12(NC) 13(NC) 15(NC); U3 1(NC) 5(NC) 10(HO) 11(NC) 12(NC) 13(NC) 15(NC); U4 1(NC) 5(NC) 8(HS) 9(HB) 10(HO) 11(NC) 12(NC) 13(NC) 15(NC); U6 1(NC) 5(NC) 10(HO) 11(NC) 12(NC) 13(NC) 15(NC)

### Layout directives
net class HV: +Filter, +Vin_Main, HO1, HO1_GAN, HO2, HO2_GAN, NetC1_1, NetC31_1, NetC35_2, NetC73_1, NetC77_2, NetR3_2, NetR4_2, NetR27_2, NetR28_2, NetR58_1, NetR59_1, NetR60_1, NetR61_1, SW1, SW2, Vbst1, Vbst2, VIN

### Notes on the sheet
- (near J3) Input Voltage = 48Vin Nominal
- (24Vin Min.; 60Vin Max.)
- 1.5uF effective @ 48Vin
- UVLO Rising/Enable = 23.0Vin
- UVLO Falling/Disable = 20.0Vin
- 5Vout @ 30A Nominal
- Fsw = 300kHz
- 40uF effective @ 5Vin
- (60A Max.)
- Place D4 close to U2
- Potential Options for Cout MLCCs:
  GCM32ER71A226KE12L (22uF; 10V; X7R; 18uF at 5V)
  GCM32EC71A476KE02K (47uF; 10V; X7S; 30uF at 5V)
- (near R22) FB Vref = 0.8V
- (near C51) PFM/SYNC pin = HIGH -> PFM
- (near C51) PFM/SYNC pin = LOW -> FPWM
- For Dual-Phase, Single Output operation: install J9, J10, and J11.
- *NOTES:
  1. D1 and D5 can be removed. The LM5148-Q1 contains internal bootstrap diodes.
  2. D3 and D7 protect the circuit from potential large negative voltages caused by short circuit applications using long lead wires on the output. These diodes may be omitted on a final system design.
- Place D8 close to U5
- FB Vref = 0.8V

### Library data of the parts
C1 = CMP-0048820-1: Cap Aluminum Lytic 390uF 80V 20% (16 X 16.5mm) SMD 0.1 Ohm 1900mA 3000h 125°C Automotive T/R; Manufacturer: Panasonic; Value: 390µF; SizeZ_mm: 17.1mm; AEC Qualified: No; IRMS_A: 1.9A; Dissipation Factor: 12%; Esr: 0.1; Leakage Current: 312uA; Life: 3000Hours
C2 = CMP-0084773-1: CAP, CERM, 0.01 µF, 100 V,+/- 10%, X7R, AEC-Q200 Grade 1, 0603; Manufacturer: MuRata; Polarized: N; Value: 0.01uF; ValueDisplayed: 0.01µF; U/M: EA; TaMin_C: -55°C; TaMax_C: 125°C; Cap_Case: 0603; AEC Category: Q200; AEC Grade: 1; AEC Qualified: Y; SizeArea_mm2: 1.28; SizeAreaWB_mm2: 4.68; SizeX_mm: 1.6; SizeY_mm: 0.8
C3 C7 = CMP-0084773-1: CAP, CERM, 0.01 µF, 100 V,+/- 10%, X7R, AEC-Q200 Grade 1, 0603; Manufacturer: MuRata; TaMin_C: -55°C; Polarized: N; SizeAreaWB_mm2: 4.68; U/M: EA; Value: 0.01uF; TaMax_C: 125°C; SizeZ_mm: 1; SizeX_mm: 1.6; SizeY_mm: 0.8; Cap_Case: 0603; SizeArea_mm2: 1.28; AEC Qualified: Y; AEC Category: Q200; ValueDisplayed: 0.01µF
C4 = CMP-0008790-2: CAP, CERM, 2.2 uF, 100 V, +/- 10%, X7S, AEC-Q200 Grade 1, 1206; Manufacturer: TDK; TaMin_C: -55°C; ESR_ohm: 5.718m; Polarized: N; SizeAreaWB_mm2: 10.92; Value1: 0.005718 ohm; U/M: EA; Value: 2.2uF; TaMax_C: 125°C; SizeZ_mm: 1.8; SizeX_mm: 3.2; SizeY_mm: 1.6; SizeArea_mm2: 5.12; AEC Qualified: Y; Cap_F: 2.2µF; IRMS_A: 3.03632A; AEC Grade: 1; AEC Category: Q200
C5 = CMP-0009134-2: CAP, CERM, 4.7 uF, 100 V, +/- 10%, X7S, 1210; Manufacturer: TDK; AEC Qualified: N; SizeZ_mm: 2.2; Cap_F: 4.7µF; TaMin_C: -55°C; ESR_ohm: 4.236m; SizeAreaWB_mm2: 14.7; Value1: 0.004236 ohm; U/M: EA; Value: 4.7uF; TaMax_C: 125°C; SizeX_mm: 3.2; SizeY_mm: 2.5; SizeArea_mm2: 8; IRMS_A: 3.57337A; AEC Category: Q200
C6 = CMP-0009150-2: CAP, CERM, 4.7 uF, 100 V, +/- 10%, X7S, AEC-Q200 Grade 1, 1210; Manufacturer: TDK; AEC Qualified: Y; SizeZ_mm: 2.2; Cap_F: 4.7µF; AEC Grade: 1; TaMin_C: -55°C; ESR_ohm: 4.236m; Polarized: N; SizeAreaWB_mm2: 14.7; Value1: 0.004236 ohm; U/M: EA; Value: 4.7uF; TaMax_C: 125°C; SizeX_mm: 3.2; SizeY_mm: 2.5; SizeArea_mm2: 8; IRMS_A: 3.57337A; AEC Category: Q200
C8 C9 = CMP-0084773-1: CAP, CERM, 0.01 µF, 100 V,+/- 10%, X7R, AEC-Q200 Grade 1, 0603; Manufacturer: MuRata; TaMin_C: -55°C; Polarized: N; SizeAreaWB_mm2: 4.68; U/M: EA; Value: 0.01uF; TaMax_C: 125°C; SizeZ_mm: 1; SizeX_mm: 1.6; SizeY_mm: 0.8; SizeArea_mm2: 1.28; AEC Qualified: Y; AEC Category: Q200; ValueDisplayed: 0.01µF
C10 C11 = CMP-0861070-1: CAP, CERM, 1 µF, 100 V,+/- 10%, X7R, AEC-Q200 Grade 1, 0805; Manufacturer: AVX; Polarized: N; Value: 1uF; U/M: EA; TaMin_C: -55°C; TaMax_C: 125°C; Cap_Case: 0805; AEC Category: Q200; AEC Grade: 1; AEC Qualified: Y; SizeArea_mm2: 2.5; SizeAreaWB_mm2: 6.75; SizeX_mm: 2; SizeY_mm: 1.25; SizeZ_mm: 1.5
C12-C16 C55-C58 C101 = CMP-0093675-1: 4.7uF ±10% 100V Ceramic Capacitor X7S 1210 (3225 Metric); Manufacturer: Murata; AEC Qualified: Yes; TempCo: 22%; SizeZ_mm: 2.3mm; Cap_F: 4.7µF; AEC Grade: Grade 1; Value: 4.7µF
C17-C20 C59-C62 = CMP-0064935-4: CAP, CERM, 0.1 uF, 100 V,+/- 10%, X7R, AEC-Q200 Grade 1, 0603; Manufacturer: MuRata; TaMin_C: -55°C; Polarized: N; SizeAreaWB_mm2: 4.68; Value1: Unknown; U/M: EA; Value: 0.1uF; TaMax_C: 125°C; SizeZ_mm: 1; SizeX_mm: 1.6; SizeY_mm: 0.8; Cap_Case: 0603; SizeArea_mm2: 1.28; AEC Qualified: Y; Cap_F: 100nF; AEC Category: Q200
C21-C24 C29 C63-C67 C103 = CMP-0093675-1: 4.7uF ±10% 100V Ceramic Capacitor X7S 1210 (3225 Metric); Manufacturer: Murata; PartNumber: GCJ32DC72A475KE01L; AEC Qualified: Yes; TempCo: 22%; SizeZ_mm: 2.3mm; Cap_F: 4.7µF; AEC Grade: Grade 1; Value: 4.7µF
C25-C28 C68-C71 = CMP-0064935-4: CAP, CERM, 0.1 uF, 100 V,+/- 10%, X7R, AEC-Q200 Grade 1, 0603; Manufacturer: MuRata; PartNumber: GCJ188R72A104KA01D; TaMin_C: -55°C; Polarized: N; SizeAreaWB_mm2: 4.68; Value1: Unknown; U/M: EA; Value: 0.1uF; TaMax_C: 125°C; SizeZ_mm: 1; SizeX_mm: 1.6; SizeY_mm: 0.8; Cap_Case: 0603; SizeArea_mm2: 1.28; AEC Qualified: Y; Cap_F: 100nF; AEC Category: Q200
C30 C72 = Capacitor: CAP, CERM, xxxF, xxV, [TempCo], xx%, [PackageReference]; Manufacturer: Kyocera AVX; Polarized: N; U/M: EA
C31 C32 C73 C74 = CMP-0006674-2: CAP, CERM, 0.01 uF, 50 V, +/- 10%, X7R, 0402; Manufacturer: MuRata; Polarized: N; Value: 0.01uF; U/M: EA; Cap_F: 10nF; Value1: Unknown; TaMin_C: -55°C; TaMax_C: 125°C; AEC Category: Q200; SizeArea_mm2: 0.5; SizeAreaWB_mm2: 3; SizeX_mm: 1; SizeZ_mm: 0.6
C33 C48 C90 = CMP-0079150-1: CAP, CERM, 0.1 µF, 10 V,+/- 10%, X7R, AEC-Q200 Grade 1, 0402; Manufacturer: Kemet; Polarized: N; ValueDisplayed: 0.1µF; U/M: EA; Cap_F: 100nF; TaMin_C: -55°C; TaMax_C: 125°C; Cap_Case: 0402; AEC Category: Q200; AEC Grade: 1; AEC Qualified: Y; SizeArea_mm2: 0.5; SizeAreaWB_mm2: 3; SizeZ_mm: 0.6
C34 C76 = CMP-0007498-4: CAP, CERM, 4.7 uF, 10 V, +/- 20%, X7R, 0603; Manufacturer: MuRata; Polarized: N; Value: 4.7uF; U/M: EA; Value1: Unknown; TaMin_C: -55°C; TaMax_C: 125°C; Cap_Case: 0603; AEC Category: Q200; SizeArea_mm2: 1.28; SizeAreaWB_mm2: 4.68; SizeX_mm: 1.6; SizeY_mm: 0.8; SizeZ_mm: 1
C35 C77 = Capacitor: CAP, CERM, 330F, 100V, C0G, 5%, 0603; Manufacturer: Murata; PartNumber: GCM1885C2A331JA16D; Polarized: N; U/M: EA
C36 C37 C78 C79 = CMP-0012661-3: CAP, Tantalum Polymer, 220 uF, 10 V, +/- 20%, 0.025 ohm, AEC-Q200 Grade 1, 7343-31 SMD; Manufacturer: Kemet; PartNumber: T598D227M010ATE025; TaMin_C: -55°C; ESR_ohm: 25m; Polarized: Y; SizeAreaWB_mm2: 58.59; Value: 220uF; TaMax_C: 125°C; SizeZ_mm: 3.1; SizeX_mm: 7.3; SizeY_mm: 4.3; Cap_Case: 7.3x4.3x3.1mm; SizeArea_mm2: 31.39; CompType: Capacitor; Cap_F: 220µF; IRMS_A: 3A; AEC Grade: 1; AEC Category: Q200
C38-C41 C43-C46 C80-C83 C85-C88 = Capacitor: CAP, CERM, 100uF, 6.3V, X7S, 20%, 1210; Manufacturer: Murata; Polarized: N; U/M: EA
C42 = CMP-0006861-4: CAP, CERM, 0.1 uF, 50 V, +/- 10%, X7R, 0603; Manufacturer: Kemet; TaMin_C: -55°C; Polarized: N; SizeAreaWB_mm2: 4.68; Value1: Unknown; U/M: EA; Value: 0.1uF; TaMax_C: 125°C; SizeZ_mm: 1; SizeX_mm: 1.6; SizeY_mm: 0.8; Cap_Case: 0603; SizeArea_mm2: 1.28; AEC Category: Q200
C47 = CMP-0006861-4: CAP, CERM, 0.1 uF, 50 V, +/- 10%, X7R, 0603; PartNumber: C0603C104K5RACTU; Manufacturer: Kemet; Polarized: N; Value: 0.1uF; U/M: EA; Cap_F: 100nF; Value1: Unknown; TaMin_C: -55°C; TaMax_C: 125°C; Cap_Case: 0603; AEC Category: Q200; SizeArea_mm2: 1.28; SizeAreaWB_mm2: 4.68; SizeX_mm: 1.6; SizeY_mm: 0.8; SizeZ_mm: 1
C49 C91 = CMP-0006306-2: CAP, CERM, 0.033 uF, 25 V, +/- 10%, X7R, AEC-Q200 Grade 1, 0402; Manufacturer: TDK; Polarized: N; U/M: EA; Cap_F: 33nF; Value1: Unknown; TaMin_C: -55°C; TaMax_C: 125°C; Cap_Case: 0402; AEC Category: Q200; AEC Grade: 1; AEC Qualified: Y; SizeArea_mm2: 0.5; SizeAreaWB_mm2: 3; SizeZ_mm: 0.6
C50 C92 = Capacitor: CAP, CERM, 0.22uF, 35V, X7R, 10%, 0402; Manufacturer: TDK; Polarized: N; U/M: EA
C51 C93 = CMP-0006311-2: CAP, CERM, 22 pF, 50 V, +/- 5%, C0G/NP0, AEC-Q200 Grade 1, 0402; Manufacturer: TDK; Polarized: N; Value: 22pF; U/M: EA; Value1: Unknown; TaMin_C: -55°C; TaMax_C: 125°C; Cap_Case: 0402; AEC Category: Q200; AEC Grade: 1; AEC Qualified: Y; SizeArea_mm2: 0.5; SizeAreaWB_mm2: 3; SizeZ_mm: 0.6
C52 = CMP-0006353-2: CAP, CERM, 0.022 uF, 25 V, +/- 10%, X7R, AEC-Q200 Grade 1, 0402; Manufacturer: MuRata; Polarized: N; U/M: EA; Cap_F: 22nF; Value1: Unknown; TaMin_C: -55°C; TaMax_C: 125°C; Cap_Case: 0402; AEC Category: Q200; AEC Grade: 1; AEC Qualified: Y; SizeArea_mm2: 0.5; SizeAreaWB_mm2: 3; SizeZ_mm: 0.6
C53 C95 = CMP-0006705-2: CAP, CERM, 270 pF, 100 V, +/- 10%, X7R, 0402; Manufacturer: MuRata; Polarized: N; Value: 270pF; U/M: EA; Value1: Unknown; TaMin_C: -55°C; TaMax_C: 125°C; Cap_Case: 0402; AEC Category: Q200; SizeArea_mm2: 0.5; SizeAreaWB_mm2: 3; SizeX_mm: 1; SizeZ_mm: 0.6
C54 C100 = CMP-0093675-1: 4.7uF ±10% 100V Ceramic Capacitor X7S 1210 (3225 Metric); Manufacturer: Murata; AEC Qualified: Yes; TempCo: 22%; SizeZ_mm: 2.3mm; Cap_F: 4.7µF; Value: 4.7µF; AEC Grade: Grade 1
C75 = CMP-0079150-1: CAP, CERM, 0.1 µF, 10 V,+/- 10%, X7R, AEC-Q200 Grade 1, 0402; Manufacturer: Kemet; Polarized: N; Value: 0.1uF; U/M: EA; Cap_F: 100nF; TaMin_C: -55°C; TaMax_C: 125°C; Cap_Case: 0402; AEC Category: Q200; AEC Grade: 1; AEC Qualified: Y; SizeArea_mm2: 0.5; SizeAreaWB_mm2: 3; SizeZ_mm: 0.6
C84 = CMP-0006861-4: CAP, CERM, 0.1 uF, 50 V, +/- 10%, X7R, 0603; Manufacturer: Kemet; TaMin_C: -55°C; Polarized: N; SizeAreaWB_mm2: 4.68; Value1: Unknown; U/M: EA; TaMax_C: 125°C; SizeZ_mm: 1; SizeX_mm: 1.6; SizeY_mm: 0.8; Cap_Case: 0603; SizeArea_mm2: 1.28; AEC Category: Q200
C89 = CMP-0006861-4: CAP, CERM, 0.1 uF, 50 V, +/- 10%, X7R, 0603; Manufacturer: Kemet; TaMin_C: -55°C; Polarized: N; SizeAreaWB_mm2: 4.68; Value1: Unknown; U/M: EA; TaMax_C: 125°C; SizeZ_mm: 1; SizeX_mm: 1.6; SizeY_mm: 0.8; Cap_Case: 0603; SizeArea_mm2: 1.28; Cap_F: 100nF; AEC Category: Q200
C94 = CMP-0006670-2: CAP, CERM, 5600 pF, 25 V, +/- 10%, X7R, 0402; PartNumber: GRM155R71E562KA01D; Manufacturer: MuRata; Polarized: N; Value: 5600pF; U/M: EA; Cap_F: 5.6nF; Value1: Unknown; TaMin_C: -55°C; TaMax_C: 125°C; Cap_Case: 0402; AEC Category: Q200; SizeArea_mm2: 0.5; SizeAreaWB_mm2: 3; SizeX_mm: 1; SizeZ_mm: 0.6
C96-C99 = CMP-0025958-3: RES, 10.0 k, 1%, 0.063 W, AEC-Q200 Grade 0, 0402; Manufacturer: Vishay-Dale; Power_W: 63mW; TempCo: 100 ppm/C; Value_Code: 10k0; EIA_Code: E96; Res_ohm: 10k; SizeX_mm: 1; SizeY_mm: 0.5; SizeZ_mm: 0.6; Value2: 0.063W; AEC Qualified: Y; VDC_V: 50V; AEC Category: Q200; AEC Grade: 0
C102 = CMP-0093675-1: 4.7uF ±10% 100V Ceramic Capacitor X7S 1210 (3225 Metric); Manufacturer: Murata; PartNumber: GCJ32DC72A475KE01L; AEC Qualified: Yes; TempCo: 22%; SizeZ_mm: 2.3mm; Cap_F: 4.7µF; Value: 4.7µF; AEC Grade: Grade 1
D1 D5 = CMP-0076946-1: Diode, Schottky, 100 V, 0.25 A, SOD-323F; Manufacturer: Nexperia; TJmax_C: 150°C; SizeAreaWB_mm2: 7.875; SizeZ_mm: 0.8; SizeArea_mm2: 3.125; SizeY_mm: 1.25; Vf_V: 850mV; Value2: 0.85V; SizeX_mm: 2.5; Green_REACh: Incomplete; AEC Category: Q101; Value1: 0.25A; Green_Lifecycle: Not Set; Io_A: 250mA; U/M: EA
D2 D6 = Zener: Diode, Zener, 5.6V, 2%, 500mW, SOD-323F; Manufacturer: Nexperia; SymbolCreator: a0412235; U/M: EA
D3 D7 = CMP-0048085-1: Diode 40 V 10A Surface Mount TO-277A (SMPC); Manufacturer: Vishay; AEC Qualified: Yes; SizeZ_mm: 1.2mm; TJmax_C: 150°C; AEC Grade: Grade 0; Cap_F: 750pF; Max Surge Forward Current: 280A; Peak Reverse Current: 100uA
D4 D8 = Diode_Schottky: Diode, Schottky, 100V, 2A, SOD-123; Manufacturer: Nexperia; U/M: EA
D9-D12 = Diode_Schottky: Diode, Schottky, 30V, 200mA, SOD-523; Manufacturer: ON Semi; U/M: EA
J1 J2 J7 J9-J11 = CMP-0055135-1: Shorting Jumper, 5.375mm, 2 Position, Tin, SMT; Manufacturer: Keystone; CNHeader: FALSE; Pitch_mm: 5.375
J3 J4 = CMP-0079575-1: Banana Jack Insul Nylon Red, TH; PartNumber: 108-0902-001; Manufacturer: Cinch Connectivity; Gender: Female; Current_A: 15A; Green_REACh: Incomplete; ContactFinish: Tin; Green_Lifecycle: Active
J5 J6 = CMP-0079574-1: Banana Jack Insul Nylon Black, TH; PartNumber: 108-0903-001; Manufacturer: Cinch Connectivity; Gender: Female; Current_A: 15A; Green_REACh: Incomplete; ContactFinish: Tin; Green_Lifecycle: Active
J8 J12 = CMP-0075405-3: Header, 100mil, 2x1, Gold, TH; Manufacturer: Samtec; Current_A: 6.3A; Green_Lifecycle: Active; Pitch_mm: 2.54; Cert_CSA: Y; Cert_VDE: N; Green_REACh: Passed; Row_Count: 1; Gender: Male; Voltage_V: 550V
L1 = CMP-0048360-1: 1 µH Shielded Molded Inductor 22 A 2.9mOhm Max Nonstandard; Manufacturer: Coilcraft; Self Resonant Frequency: 46MHz; AEC Grade: Grade 1; Isat: 11A; Tolerance_%: 20%; DCR_ohm: 2.9m; Ind_H: 1µH; Irms: 22A; Material: Composite; SizeZ_mm: 6.1mm; Test Frequency: 1MHz; Shrouded: true; TaMin_C: -40°C; TaMax_C: +125°C; AEC Qualified: Yes
L2 = CMP-0084691-1: Coupled inductor,  ohm, AEC-Q200 Grade 1, SMD; Manufacturer: TDK; AEC Grade: 1; AEC Category: Q200; SizeZ_mm: 6; SizeX_mm: 12; AEC Qualified: Y; SizeAreaWB_mm2: 182; SizeArea_mm2: 132; SizeY_mm: 11
L3 = CMP-0013197-2: Coupled inductor, 2 uH,  A, 1.8 ohm, SMD; Manufacturer: MuRata; SizeAreaWB_mm2: 128.14; DCR_ohm: 1.8; Value: 2uH; SizeZ_mm: 9.4; SizeX_mm: 6.6; SizeY_mm: 12.9; SizeArea_mm2: 85.14; Ind_H: 2µH
L4 L6 = CMP-0060945-1: Inductor, Shielded, Composite, 1.5 uH, 36.6 A, 0.0016 ohm, SMD; Manufacturer: Coilcraft; DCR_ohm: 1.6m; Ind_H: 1.5µH; Irms: 40.5A @ 40C rise; Isat: 36.6A @ 30% inductance drop; SizeZ_mm: 10; Green_Lifecycle: Not Set; SizeAreaWB_mm2: 159.6; Green_REACh: Incomplete; Imax_A: 36.6A; SizeX_mm: 11.3; SizeArea_mm2: 113; AEC Category: Q200
L5 L7 = CMP-0047844-1: Power Choke Coil 2.5uH 20% 100kHz 2.53mOhm 32A AECQ200 13.3x12.8x8.0mm SMT; Manufacturer: CYNTEC; Isat: 30A; DCR_ohm: 2.53m; Material: Metal Dust; SizeZ_mm: 8mm; Ind_H: 2.5µH; AEC Qualified: Yes; AEC Grade: Grade 0
NT1-NT5 = CMP-0078142-3: Single point connection between nets.
R1 R2 = CMP-0015904-3: RES, 1.0, 5%, 1 W, AEC-Q200 Grade 0, 2512; Manufacturer: Vishay-Dale; Power_W: 1W; TempCo: 200 ppm/C; Value_Code: 1R00; Value: 1.0; EIA_Code: E24; Res_ohm: 1; SizeX_mm: 6.3; SizeY_mm: 3.2; SizeZ_mm: 0.71; SizeArea_mm2: 20.16; AEC Qualified: Y; VDC_V: 500V; AEC Grade: 0; AEC Category: Q200
R3 R4 R21 R27 R28 R31 R32 R43 R47 R49 = CMP-0081856-1: RES, 0, 0%, 0.2 W, AEC-Q200 Grade 0, 0402; Manufacturer: Vishay-Dale; SizeAreaWB_mm2: 3; SizeArea_mm2: 0.5; AEC Qualified: Y; AEC Category: Q200; Value: 0; SizeZ_mm: 0.6; Power_W: 200mW; VDC_V: 50V; Value2: 0.2W; SizeX_mm: 1
R5 R30 R66 R67 = CMP-0046355-1: Res Current Sense Thick Film 1225 0.5m Ohm 5% 2W ±150ppm/°C Molded Emboss T/R; Manufacturer: Rohm Semiconductor; PartNumber: PML100HZPJV0L5; AEC Grade: Grade 0; AEC Qualified: Yes; SizeZ_mm: 0.65mm
R6 = CMP-0022060-4: RES, 150 k, 1%, 0.1 W, AEC-Q200 Grade 0, 0603; Manufacturer: Vishay-Dale; Power_W: 100mW; TempCo: 100 ppm/C; Value: 150k; EIA_Code: E96; SizeX_mm: 1.6; SizeY_mm: 0.8; SizeZ_mm: 1; Value2: 0.1W; SizeArea_mm2: 1.28; AEC Qualified: Y; VDC_V: 75V; AEC Category: Q200; AEC Grade: 0
R7 = CMP-0081856-1: RES, 0, 0%, 0.2 W, AEC-Q200 Grade 0, 0402; Manufacturer: Vishay-Dale; Value: 0; Power_W: 200mW; Value2: 0.2W; VDC_V: 50V; AEC Category: Q200; AEC Qualified: Y; SizeArea_mm2: 0.5; SizeX_mm: 1; SizeZ_mm: 0.6; SizeAreaWB_mm2: 3
R8 R33 = CMP-0001672-1: 1.2 mOhms ±1% 5W Chip Resistor 2512 (6432 Metric) Automotive AEC-Q200, Current Sense, Non-Inductive Metal Element; Manufacturer: Vishay Foil Resistors; Value: 1.2m; AEC Qualified: Yes; AEC Grade: Grade 0
R9 = CMP-0026517-2: RES, 6.81 k, 1%, 0.063 W, AEC-Q200 Grade 0, 0402; Manufacturer: Vishay-Dale; Power_W: 63mW; TempCo: 100 ppm/C; Value_Code: 6k81; Value: 6.81k; EIA_Code: E96; SizeX_mm: 1; SizeY_mm: 0.5; SizeZ_mm: 0.6; Value2: 0.063W; AEC Qualified: Y; VDC_V: 50V; AEC Category: Q200; AEC Grade: 0
R10 R19 R46 = CMP-0026753-1: RES, 100 k, 1%, 0.063 W, AEC-Q200 Grade 0, 0402; PartNumber: RMCF0402FT100K; Manufacturer: Stackpole Electronics Inc; Value: 100k; Power_W: 63mW; Value2: 0.063W; VDC_V: 50V; TempCo: 100 ppm/C; EIA_Code: E96; AEC Category: Q200; AEC Grade: 0; AEC Qualified: Y; SizeArea_mm2: 0.5; SizeX_mm: 1; SizeZ_mm: 0.6; U/M: EA
R11 R16 R36 R41 = Resistor: RES, xxx ohm, x%, xW, [PackageReference]; Manufacturer: Used in BOM report; U/M: EA
R12 R37 = CMP-0026404-2: RES, 49.9, 1%, 0.063 W, AEC-Q200 Grade 0, 0402; Manufacturer: Vishay-Dale; Value: 49.9; Value_Code: 49R9; Power_W: 63mW; Value2: 0.063W; VDC_V: 50V; TempCo: 100 ppm/C; EIA_Code: E96; AEC Category: Q200; AEC Grade: 0; AEC Qualified: Y; SizeArea_mm2: 0.5; SizeX_mm: 1; SizeZ_mm: 0.6
R13 R38 = CMP-0086542-2: RMCF/RMCP Series General Purpose Thick Film Standard Power and High Power Chip Resistor; Manufacturer: Stackpole
R14 R39 = Resistor: RES, 1.0 ohm, 5%, 0.5W, 1210; Manufacturer: Stackpole; PartNumber: RMCF1210JT4R70; U/M: EA
R15 R20 R40 R45 R58-R63 = CMP-0081856-1: RES, 0, 0%, 0.2 W, AEC-Q200 Grade 0, 0402; PartNumber: CRCW04020000Z0EDHP; Manufacturer: Vishay-Dale; SizeAreaWB_mm2: 3; SizeArea_mm2: 0.5; AEC Qualified: Y; AEC Category: Q200; Value: 0; SizeZ_mm: 0.6; Power_W: 200mW; VDC_V: 50V; Value2: 0.2W; SizeX_mm: 1
R17 = CMP-0022448-4: RES, 49.9, 1%, 0.1 W, AEC-Q200 Grade 0, 0603; Manufacturer: Vishay-Dale; Value: 49.9; Value_Code: 49R9; Power_W: 100mW; Value2: 0.1W; VDC_V: 75V; TempCo: 100 ppm/C; EIA_Code: E96; AEC Category: Q200; AEC Grade: 0; AEC Qualified: Y; SizeArea_mm2: 1.28; SizeX_mm: 1.6; SizeY_mm: 0.8; SizeZ_mm: 1
R18 R44 = CMP-0026539-2: RES, 73.2 k, 1%, 0.063 W, AEC-Q200 Grade 0, 0402; Manufacturer: Vishay-Dale; Value: 73.2k; Value_Code: 73k2; Power_W: 63mW; Value2: 0.063W; VDC_V: 50V; TempCo: 100 ppm/C; EIA_Code: E96; AEC Category: Q200; AEC Grade: 0; AEC Qualified: Y; SizeArea_mm2: 0.5; SizeX_mm: 1; SizeZ_mm: 0.6
R22 = CMP-0026399-2: RES, 48.7 k, 1%, 0.063 W, AEC-Q200 Grade 0, 0402; Manufacturer: Vishay-Dale; PartNumber: CRCW040248K7FKED; Power_W: 63mW; TempCo: 100 ppm/C; Value_Code: 48k7; Value: 48.7k; EIA_Code: E96; SizeX_mm: 1; SizeY_mm: 0.5; SizeZ_mm: 0.6; Value2: 0.063W; AEC Qualified: Y; VDC_V: 50V; AEC Category: Q200; AEC Grade: 0
R23 = CMP-0026753-1: RES, 100 k, 1%, 0.063 W, AEC-Q200 Grade 0, 0402; Manufacturer: Stackpole Electronics Inc; Power_W: 63mW; TempCo: 100 ppm/C; Value: 100k; EIA_Code: E96; SizeX_mm: 1; SizeY_mm: 0.5; SizeZ_mm: 0.6; Value2: 0.063W; AEC Qualified: Y; VDC_V: 50V; AEC Category: Q200; AEC Grade: 0; U/M: EA
R24 = CMP-0026329-2: RES, 3.01 k, 1%, 0.063 W, AEC-Q200 Grade 0, 0402; Manufacturer: Vishay-Dale; Value: 3.01k; Value_Code: 3k01; Power_W: 63mW; Value2: 0.063W; VDC_V: 50V; TempCo: 100 ppm/C; EIA_Code: E96; AEC Category: Q200; AEC Grade: 0; AEC Qualified: Y; SizeArea_mm2: 0.5; SizeX_mm: 1; SizeZ_mm: 0.6
R25 = CMP-0026449-2: RES, 54.9 k, 1%, 0.063 W, AEC-Q200 Grade 0, 0402; Manufacturer: Vishay-Dale; Value: 54.9k; Value_Code: 54k9; Power_W: 63mW; Value2: 0.063W; VDC_V: 50V; TempCo: 100 ppm/C; EIA_Code: E96; AEC Category: Q200; AEC Grade: 0; AEC Qualified: Y; SizeArea_mm2: 0.5; SizeX_mm: 1; SizeZ_mm: 0.6
R26 = CMP-0026067-3: RES, 19.1 k, 1%, 0.063 W, AEC-Q200 Grade 0, 0402; Manufacturer: Vishay-Dale; Power_W: 63mW; TempCo: 100 ppm/C; Value_Code: 19k1; Value: 19.1k; EIA_Code: E96; SizeX_mm: 1; SizeY_mm: 0.5; SizeZ_mm: 0.6; Value2: 0.063W; AEC Qualified: Y; VDC_V: 50V; AEC Category: Q200; AEC Grade: 0
R29 = CMP-0021990-4: RES, 100 k, 1%, 0.1 W, AEC-Q200 Grade 0, 0603; Manufacturer: Vishay-Dale; PartNumber: CRCW0603100KFKEA; Power_W: 100mW; TempCo: 100 ppm/C; Value: 100k; EIA_Code: E96; SizeX_mm: 1.6; SizeY_mm: 0.8; SizeZ_mm: 1; Value2: 0.1W; SizeArea_mm2: 1.28; AEC Qualified: Y; VDC_V: 75V; AEC Category: Q200; AEC Grade: 0
R34 = CMP-0026412-2: RES, 4.75 k, 1%, 0.063 W, AEC-Q200 Grade 0, 0402; Manufacturer: Vishay-Dale; PartNumber: CRCW04024K75FKED; Power_W: 63mW; TempCo: 100 ppm/C; Value_Code: 4k75; Value: 4.75k; EIA_Code: E96; SizeX_mm: 1; SizeY_mm: 0.5; SizeZ_mm: 0.6; Value2: 0.063W; AEC Qualified: Y; VDC_V: 50V; AEC Category: Q200; AEC Grade: 0
R35 = CMP-0026753-1: RES, 100 k, 1%, 0.063 W, AEC-Q200 Grade 0, 0402; Manufacturer: Stackpole Electronics Inc; Value: 100k; Power_W: 63mW; Value2: 0.063W; VDC_V: 50V; TempCo: 100 ppm/C; EIA_Code: E96; AEC Category: Q200; AEC Grade: 0; AEC Qualified: Y; SizeArea_mm2: 0.5; SizeX_mm: 1; SizeZ_mm: 0.6; U/M: EA
R42 = CMP-0022448-4: RES, 49.9, 1%, 0.1 W, AEC-Q200 Grade 0, 0603; PartNumber: CRCW060349R9FKEA; Manufacturer: Vishay-Dale; Value: 49.9; Value_Code: 49R9; Power_W: 100mW; Value2: 0.1W; VDC_V: 75V; TempCo: 100 ppm/C; EIA_Code: E96; AEC Category: Q200; AEC Grade: 0; AEC Qualified: Y; SizeArea_mm2: 1.28; SizeX_mm: 1.6; SizeY_mm: 0.8; SizeZ_mm: 1
R48 = CMP-0026555-2: RES, 7.50 k, 1%, 0.063 W, AEC-Q200 Grade 0, 0402; PartNumber: CRCW04027K50FKED; Manufacturer: Vishay-Dale; Value: 7.50k; Res_ohm: 7.5k; Value_Code: 7k50; Power_W: 63mW; Value2: 0.063W; VDC_V: 50V; TempCo: 100 ppm/C; EIA_Code: E96; AEC Category: Q200; AEC Grade: 0; AEC Qualified: Y; SizeArea_mm2: 0.5; SizeX_mm: 1; SizeZ_mm: 0.6
R50 = CMP-0026753-1: RES, 100 k, 1%, 0.063 W, AEC-Q200 Grade 0, 0402; Manufacturer: Stackpole Electronics Inc; PartNumber: RMCF0402FT100K; Power_W: 63mW; TempCo: 100 ppm/C; Value: 100k; EIA_Code: E96; SizeX_mm: 1; SizeY_mm: 0.5; SizeZ_mm: 0.6; Value2: 0.063W; AEC Qualified: Y; VDC_V: 50V; AEC Category: Q200; AEC Grade: 0; U/M: EA
R51 R53 = CMP-0086542-2: RMCF/RMCP Series General Purpose Thick Film Standard Power and High Power Chip Resistor; Manufacturer: Stackpole; PartNumber: RMCF0402ZT0R00
R52 = CMP-0026605-2: RES, 90.9 k, 1%, 0.063 W, AEC-Q200 Grade 0, 0402; Manufacturer: Vishay-Dale; Value: 90.9k; Value_Code: 90k9; Power_W: 63mW; Value2: 0.063W; VDC_V: 50V; TempCo: 100 ppm/C; EIA_Code: E96; AEC Category: Q200; AEC Grade: 0; AEC Qualified: Y; SizeArea_mm2: 0.5; SizeX_mm: 1; SizeZ_mm: 0.6
R54-R57 = CMP-0026357-2: RES, 3.32, 1%, 0.063 W, AEC-Q200 Grade 0, 0402; Manufacturer: Vishay-Dale; Power_W: 63mW; TempCo: 100 ppm/C; Value_Code: 3R32; Value: 3.32; SizeX_mm: 1; SizeY_mm: 0.5; SizeZ_mm: 0.6; Value2: 0.063W; AEC Qualified: Y; EIA_Code: E96; VDC_V: 50V; AEC Category: Q200; AEC Grade: 0
R64 R65 = CMP-0001672-1: 1.2 mOhms ±1% 5W Chip Resistor 2512 (6432 Metric) Automotive AEC-Q200, Current Sense, Non-Inductive Metal Element; Manufacturer: Vishay Foil Resistors; PartNumber: Y14830R00120F9R; Value: 1.2m; AEC Qualified: Yes; AEC Grade: Grade 0
SH-J1 SH-J2 = CMP-0003761-2: Shunt, 2.54mm, Gold, Black; Manufacturer: Wurth Elektronik
T1-T3 = CMP-0055443-2: Terminal 90A Lug; Manufacturer: Panduit; Green_Lifecycle: Not Set; Cert_CULUS: Y; Green_REACh: Incomplete; Voltage_V: 600V; CompType: Screw Terminal; ContactFinish: Copper
TP1 TP2 = CMP-0055153-2: Test Point, Compact, SMT; Manufacturer: Keystone Electronics; Green_Lifecycle: Active; Green_REACh: Passed; CNHeader: FALSE; CT: TRUE
TP3 TP9 = CMP-0055147-1: Test Point, Multipurpose, Red, TH; Manufacturer: Keystone; CNHeader: FALSE; Green_Lifecycle: Active; Green_REACh: Passed; ContactFinish: Silver; CT: TRUE
TP4-TP6 TP10-TP12 = CMP-0055149-1: Test Point, Multipurpose, White, TH; Manufacturer: Keystone; CNHeader: FALSE; Green_Lifecycle: Active; Green_REACh: Passed; ContactFinish: Silver; CT: TRUE
TP7 TP8 = CMP-0055148-1: Test Point, Multipurpose, Black, TH; Manufacturer: Keystone; CNHeader: FALSE; Green_Lifecycle: Active; Green_REACh: Passed; ContactFinish: Silver; CT: TRUE
U1 U3 U4 U6 = CMP-0037654-1: 100-V, 64-A GaN with Integrated Driver; Manufacturer: Texas Instruments; SizeZ_mm: 0.85mm; AEC Qualified: No; Max Supply Voltage: 5.25V; Min Supply Voltage: 4.75V; Nominal Supply Current: 3mA; Number Of Drivers: 1; Propagation Delay: 55ns; Standoff Height: 0mm; TJmax_C: +125°C
U2 U5 = CMP-0120564-1: 80-V, Automotive, Synchronous, Buck DC/DC Controller with Ultra-Low IQ and Dual Random Spread Spectrum; Manufacturer: Texas Instruments; SizeZ_mm: 1mm; AEC Qualified: Yes; AEC Grade: Grade 1; Max Duty Cycle: 100%; Max Supply Voltage: 80V; Min Supply Voltage: 3.5V; Nominal Supply Current: 9.5-124uA; Number Of Outputs: 1; Output Type: Fixed,AdjustableProgrammable; Output Voltage: 3.3/5/12/0.8-55V; Standoff Height: 0mm; Switching Frequency: 0.1-2.2MHz; TaMax_C: +125°C; TaMin_C: -40°C; TJmax_C: +150°C

## Sheet PMP23392_Hardware.SchDoc
size 431 x 279 mm; Date: Not shown in title block; ApprovedBy: Not shown in title block; CheckedBy: Not shown in title block; Author: Not shown in title block; CompanyName: Not shown in title block; Engineer: Not shown in title block; Organization: Not shown in title block; Address1: Not shown in title block; Address2: Not shown in title block; Address3: Not shown in title block; Address4: Not shown in title block; DocumentNumber: 2; Revision: Use project parameter SCH_Rev; SheetNumber: 2; SheetTotal: 2; PageSetup: Record=PageOptions¦CenterHorizontal=True¦CenterVertical=True¦PrintScale=1.00¦XCorrection=1.00¦YCorrection=1.00¦PrintKind=0¦BorderSize=5000000¦LeftOffset=0¦BottomOffset=0¦Orientation=2¦PaperLength=1000¦PaperWidth=1000¦Scale=100¦PaperSource=15¦PrintQuality=600¦MediaType=1¦DitherType=10¦PaperKind=Letter¦PrintScaleMode=1
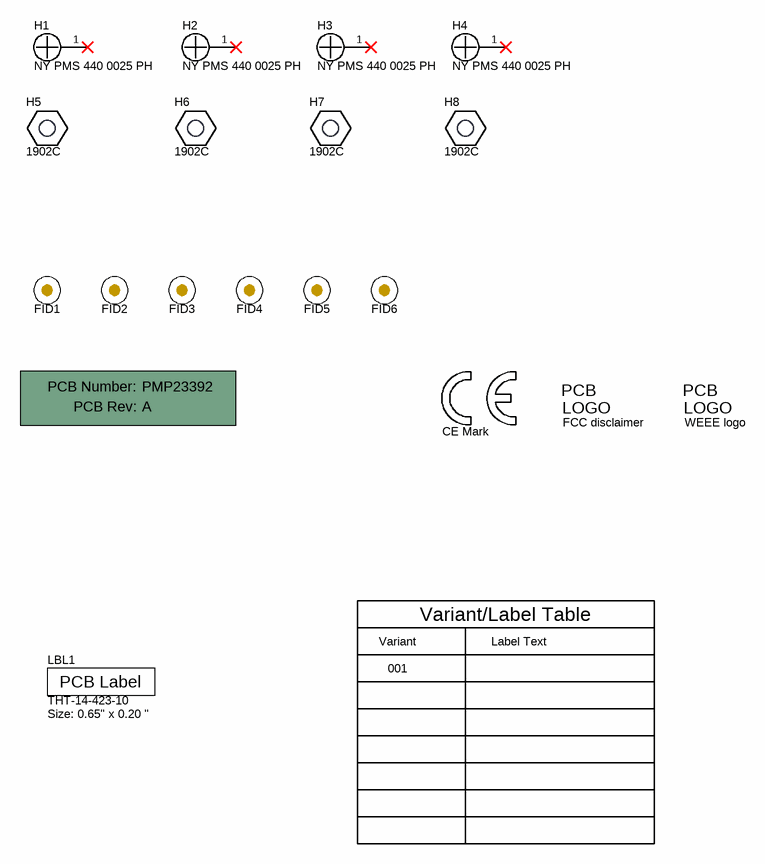
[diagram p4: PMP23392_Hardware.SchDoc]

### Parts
!PCB1  Printed Circuit Board  (value not drawn)  (mechanical)
FID1  Fiducial  [Fiducial10-20]  (value not drawn)
FID2  Fiducial  [Fiducial10-20]  (value not drawn)
FID3  Fiducial  [Fiducial10-20]  (value not drawn)
FID4  Fiducial  [Fiducial10-20]  (value not drawn)
FID5  Fiducial  [Fiducial10-20]  (value not drawn)
FID6  Fiducial  [Fiducial10-20]  (value not drawn)
H1  NY PMS 440 0025 PH  [NY PMS 440 0025 PH]
H2  NY PMS 440 0025 PH  [NY PMS 440 0025 PH]
H3  NY PMS 440 0025 PH  [NY PMS 440 0025 PH]
H4  NY PMS 440 0025 PH  [NY PMS 440 0025 PH]
H5  1902C  [Keystone_1902C]
H6  1902C  [Keystone_1902C]
H7  1902C  [Keystone_1902C]
H8  1902C  [Keystone_1902C]
LBL1  THT-14-423-10  Note: Size: 0.65" x 0.20 "  [Label_650x200]
Logo1  CE Mark  [CE_Mark_5mm]  (no BOM)
Logo2  FCC disclaimer  [FCC_disclaimer]  (no BOM)
Logo3  WEEE logo  [WEEE_Minimum]  (no BOM)

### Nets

Not connected (* = marked no-connect by the designer): H1 1*; H2 1*; H3 1*; H4 1*

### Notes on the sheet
- Variant
- Variant/Label Table
- Label Text
- 001

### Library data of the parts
!PCB1 = CMP-0003618-2: Manufacturer: Any; PartNumber: PMP23392
FID1-FID6 = CMP-0077181-1: Fiducial mark.  There is nothing to buy or mount.
H1-H4 = CMP-0003617-1: Machine Screw, Round, #4-40 x 1/4, Nylon, Philips panhead; Manufacturer: B&F Fastener Supply; CompType: Hardware
H5-H8 = CMP-0003610-1: Standoff, Hex, 0.5"L #4-40 Nylon; Manufacturer: Keystone; CompType: Hardware
LBL1 = CMP-0003625-1: Thermal Transfer Printable Labels, 0.650" W x 0.200" H - 10,000 per roll; Manufacturer: Brady; CompType: Label
Logo1 = CMP-0074844-1: SymbolCreator: a0412235
Logo2 = CMP-0074847-1: FCC_disclaimer; Library Reference: Logo
Logo3 = CMP-0074769-1

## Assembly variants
001: not fitted C21 C22 C23 C24 C25 C26 C27 C28 C29 C35 C63 C64 C65 C66 C67 C68 C69 C70 C71 C77 C94 C102 C103 D4 D8 D9 D10 D11 D12 FID1 FID2 FID3 FID4 FID5 FID6 L1 L2 L3 L5 L7 R5 R10 R11 R14 R15 R16 R19 R22 R29 R30 R34 R36 R39 R40 R41 R42 R45 R46 R48 R50 R51 R58 R59 R60 R61 R64 R65 R66 R67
